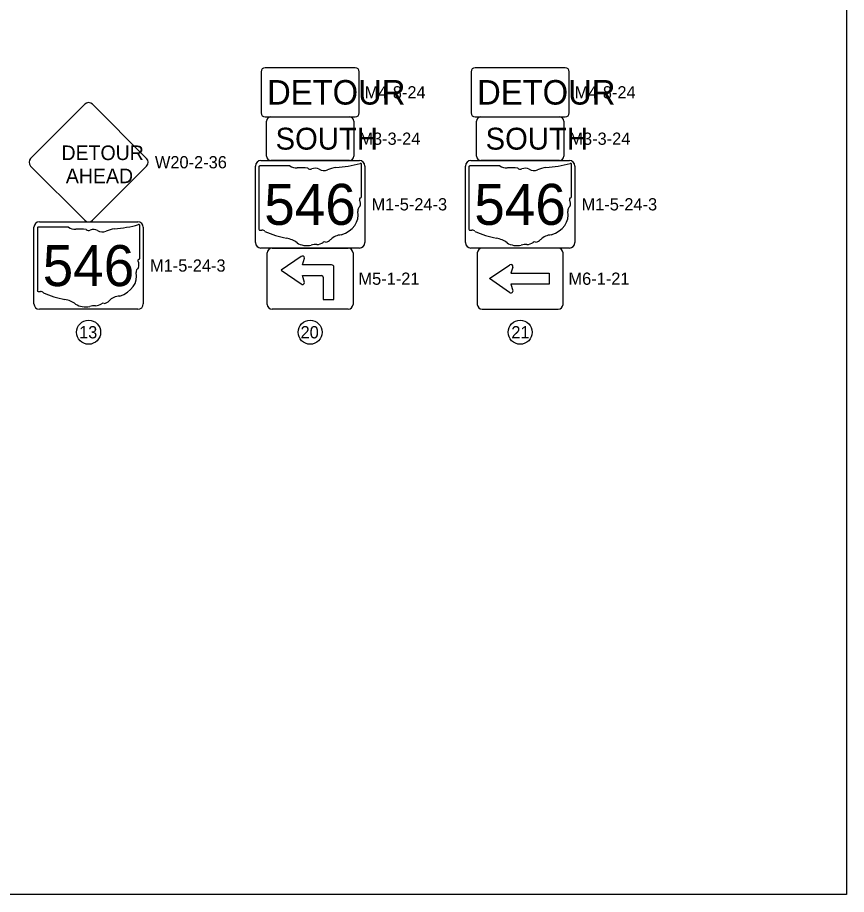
# Model space of a CAD drawing. Extents: x 40529 to 41139, y 15164 to 15584.
# Drawn here: x 40949.2 to 41138.7, y 15164.3 to 15364.8 of the extents above; entities that cross this region are included whole.
import ezdxf

# ---------------------------------------------------------------- set-up
doc = ezdxf.new("R2010")
doc.units = 0
for name, color, linetype in [('SC_Scratch1', 7, 'Continuous'), ('SH_Text', 7, 'Continuous'), ('SN_P_Signs', 7, 'Continuous'), ('SN_P_Text', 7, 'Continuous')]:
    doc.layers.add(name, color=color, linetype=linetype)

msp = doc.modelspace()

# ---------------------------------------------------------------- linework, layer by layer
at = {"layer": 'SC_Scratch1'}
msp.add_lwpolyline([(40528.65, 15584.31), (41138.65, 15584.31), (41138.65, 15164.31), (40528.65, 15164.31)], close=True, dxfattribs=at)
at = {"layer": 'SH_Text'}
for p, q in [((41007.4, 15312.09), (41024.76, 15312.09)), ((41072.76, 15312.09), (41055.4, 15312.09)), ((41072.76, 15312.09), (41072.76, 15312.09)), ((41006.28, 15299.21), (41006.28, 15310.97)), ((41014, 15310.14), (41009.43, 15307.01)), ((41025.88, 15310.97), (41025.88, 15299.21)), ((41054.28, 15310.97), (41054.28, 15299.21)), ((41073.88, 15299.21), (41073.88, 15310.97)), ((41014.33, 15308.23), (41014.8, 15309.81)), ((41020.98, 15308.23), (41014.33, 15308.23)), ((41020.98, 15308.23), (41020.98, 15308.23)), ((41057.08, 15305.09), (41061.72, 15308.27)), ((41009.43, 15307.01), (41014, 15303.88)), ((41021.51, 15300.36), (41021.51, 15307.71)), ((41062.43, 15307.75), (41061.98, 15306.31)), ((41061.98, 15306.31), (41070.73, 15306.31)), ((41070.73, 15306.31), (41070.73, 15303.86)), ((41014.8, 15304.21), (41014.33, 15305.78)), ((41014.33, 15305.78), (41018.71, 15305.78)), ((41019.06, 15305.43), (41019.06, 15300.36)), ((41061.65, 15301.95), (41057.08, 15305.09)), ((41070.73, 15303.86), (41061.98, 15303.86)), ((41061.98, 15303.86), (41062.43, 15302.42)), ((41019.06, 15300.36), (41021.51, 15300.36)), ((41019.06, 15300.36), (41021.51, 15300.36)), ((41024.76, 15298.09), (41007.4, 15298.09)), ((41055.4, 15298.09), (41072.76, 15298.09))]:
    msp.add_line(p, q, dxfattribs=at)
for points in [[(41004.88, 15352.39), (41004.88, 15342.98)], [(41026.39, 15353.29), (41005.78, 15353.29)], [(41027.28, 15342.98), (41027.28, 15352.39)], [(41052.88, 15352.39), (41052.88, 15342.98)], [(41074.39, 15353.29), (41053.78, 15353.29)], [(41075.28, 15342.98), (41075.28, 15352.39)], [(41005.78, 15342.09), (41026.39, 15342.09)], [(41053.78, 15342.09), (41074.39, 15342.09)]]:
    msp.add_lwpolyline(points, dxfattribs=at)
for centre in [(40965.45, 15292.84), (41016.08, 15292.84), (41064.08, 15292.84)]:
    msp.add_circle(centre, 2.75, dxfattribs=at)
for centre, radius, start, end in [((41005.78, 15352.39), 0.896, 90, 180), ((41026.39, 15352.39), 0.896, 0, 90), ((41053.78, 15352.39), 0.896, 90, 180), ((41074.39, 15352.39), 0.896, 0, 90), ((41005.78, 15342.98), 0.896, 180, 270), ((41026.39, 15342.98), 0.896, 270, 0), ((41053.78, 15342.98), 0.896, 180, 270), ((41074.39, 15342.98), 0.896, 270, 0), ((41007.4, 15310.97), 1.12, 90, 180), ((41024.76, 15310.97), 1.12, 0, 90), ((41055.4, 15310.97), 1.12, 90, 180), ((41072.76, 15310.97), 1.12, 0, 90), ((41014.33, 15309.81), 0.467, 0.0017, 134.9999), ((41020.98, 15307.71), 0.525, 0, 90), ((41061.98, 15307.89), 0.467, 342.7954, 124.5888), ((41014.33, 15304.21), 0.467, 225.0001, 0.0017), ((41018.71, 15305.43), 0.349, 0, 90), ((41061.98, 15302.29), 0.467, 224.9904, 17.2046), ((41007.4, 15299.21), 1.12, 180, 270), ((41024.76, 15299.21), 1.12, 270, 360), ((41055.4, 15299.21), 1.12, 180, 270), ((41072.76, 15299.21), 1.12, 270, 0)]:
    msp.add_arc(centre, radius, start, end, dxfattribs=at)
at = {"layer": 'SN_P_Signs'}
for p, q in [((41006.08, 15333.09), (41006.08, 15341.09)), ((41007.08, 15342.09), (41025.08, 15342.09)), ((41026.08, 15341.09), (41026.08, 15333.09)), ((41054.08, 15333.09), (41054.08, 15341.09)), ((41055.08, 15342.09), (41073.08, 15342.09)), ((41074.08, 15341.09), (41074.08, 15333.09)), ((41025.08, 15332.09), (41007.08, 15332.09)), ((41073.08, 15332.09), (41055.08, 15332.09)), ((41004.36, 15330.61), (41004.36, 15316.38)), ((41011.46, 15330.86), (41004.59, 15330.86)), ((41027.8, 15323.77), (41027.8, 15331.21)), ((41052.36, 15330.61), (41052.36, 15316.38)), ((41059.46, 15330.86), (41052.59, 15330.86)), ((41075.8, 15323.77), (41075.8, 15331.21)), ((41027.8, 15323.77), (41027.8, 15323.77)), ((41075.8, 15323.77), (41075.8, 15323.77)), ((40953.73, 15316.61), (40953.73, 15302.38)), ((40960.83, 15316.86), (40953.96, 15316.86)), ((40977.17, 15309.77), (40977.17, 15317.21)), ((40977.17, 15309.77), (40977.17, 15309.77))]:
    msp.add_line(p, q, dxfattribs=at)
for points in [[(40952.19, 15332.59), (40964.57, 15344.97)], [(40966.34, 15344.97), (40978.71, 15332.59)], [(41004.83, 15332.09), (41027.33, 15332.09)], [(41052.83, 15332.09), (41075.33, 15332.09)], [(40964.57, 15318.45), (40952.19, 15330.83)], [(40978.71, 15330.83), (40966.34, 15318.45)], [(41003.58, 15313.34), (41003.58, 15330.84)], [(41028.58, 15330.84), (41028.58, 15313.34)], [(41051.58, 15313.34), (41051.58, 15330.84)], [(41076.58, 15330.84), (41076.58, 15313.34)], [(40954.2, 15318.09), (40976.7, 15318.09)], [(40952.95, 15299.34), (40952.95, 15316.84)], [(40977.95, 15316.84), (40977.95, 15299.34)], [(41027.33, 15312.09), (41004.83, 15312.09)], [(41075.33, 15312.09), (41052.83, 15312.09)], [(40976.7, 15298.09), (40954.2, 15298.09)]]:
    msp.add_lwpolyline(points, dxfattribs=at)
for centre, radius, start, end in [((40965.45, 15344.08), 1.25, 45, 135), ((41007.08, 15341.08), 1, 90, 180), ((41025.08, 15341.08), 1, 0, 90), ((41055.08, 15341.08), 1, 90, 180), ((41073.08, 15341.08), 1, 0, 90), ((40953.08, 15331.71), 1.25, 135, 225), ((40977.83, 15331.71), 1.25, 315, 45), ((41004.83, 15330.84), 1.25, 90, 180), ((41007.08, 15333.08), 1, 180, 270), ((41025.08, 15333.08), 1, 270, 0), ((41027.33, 15330.84), 1.25, 0, 90), ((41052.83, 15330.84), 1.25, 90, 180), ((41055.08, 15333.08), 1, 180, 270), ((41073.08, 15333.08), 1, 270, 0), ((41075.33, 15330.84), 1.25, 0, 90), ((40954.2, 15316.84), 1.25, 90, 180), ((40965.45, 15319.34), 1.25, 225, 315), ((40976.7, 15316.84), 1.25, 0, 90), ((41004.83, 15313.34), 1.25, 180, 270), ((41027.33, 15313.34), 1.25, 270, 0), ((41052.83, 15313.34), 1.25, 180, 270), ((41075.33, 15313.34), 1.25, 270, 0), ((40954.2, 15299.34), 1.25, 180, 270), ((40976.7, 15299.34), 1.25, 270, 0)]:
    msp.add_arc(centre, radius, start, end, dxfattribs=at)
for centre, major_axis, start_param, end_param in [((41004.63, 15330.64), (0.272, 0), 1.712693, 3.28349), ((41013.09, 15332.51), (2.63, 0), 4.042523, 4.731795), ((41013.97, 15322.87), (9.45, 0), 1.404758, 1.657858), ((41016.11, 15330.72), (0.76, 0), 3.836095, 5.185415), ((41017.23, 15329.07), (1.58, 0), 0.950623, 2.079405), ((41019.27, 15331.33), (1.9, 0), 4.081561, 5.145723), ((41022.62, 15326.51), (5, 0), 1.699011, 2.107814), ((41019.45, 15350.26), (24.85, 0), 4.814394, 5.042369), ((41027.54, 15331.24), (0.261, 0), 6.141152, 7.989035), ((41052.63, 15330.64), (0.272, 0), 1.712693, 3.28349), ((41061.09, 15332.51), (2.63, 0), 4.042523, 4.731795), ((41061.97, 15322.87), (9.45, 0), 1.404758, 1.657858), ((41064.11, 15330.72), (0.76, 0), 3.836095, 5.185415), ((41065.23, 15329.07), (1.58, 0), 0.950623, 2.079405), ((41067.27, 15331.33), (1.9, 0), 4.081561, 5.145723), ((41070.62, 15326.51), (5, 0), 1.699011, 2.107814), ((41067.45, 15350.26), (24.85, 0), 4.814394, 5.042369), ((41075.54, 15331.24), (0.261, 0), 6.141152, 7.989035), ((41027.74, 15323.22), (0.404, 0), 1.883978, 3.671073), ((41025.17, 15322.28), (2.42, 0), 5.934695, 6.695948), ((41027.52, 15323.74), (0.279, 0), 5.05454, 6.418171), ((41075.74, 15323.22), (0.404, 0), 1.883978, 3.671073), ((41073.17, 15322.28), (2.42, 0), 5.934695, 6.695948), ((41075.52, 15323.74), (0.279, 0), 5.05454, 6.418171), ((41020.84, 15319.7), (6.22, 0), 5.101752, 6.440018), ((41028.74, 15320.65), (1.76, 0), 2.387724, 3.262537), ((41068.84, 15319.7), (6.22, 0), 5.101752, 6.440018), ((41076.74, 15320.65), (1.76, 0), 2.387724, 3.262537), ((40954, 15316.64), (0.272, 0), 1.712693, 3.28349), ((40962.46, 15318.51), (2.63, 0), 4.042523, 4.731795), ((40963.33, 15308.87), (9.45, 0), 1.404758, 1.657858), ((40965.48, 15316.72), (0.76, 0), 3.836095, 5.185415), ((40966.6, 15315.07), (1.58, 0), 0.950623, 2.079405), ((40968.63, 15317.33), (1.9, 0), 4.081561, 5.145723), ((40971.99, 15312.51), (5, 0), 1.699011, 2.107814), ((40968.82, 15336.26), (24.85, 0), 4.814394, 5.042369), ((40976.91, 15317.24), (0.261, 0), 6.141152, 7.989035), ((41004.63, 15316.35), (0.274, 0), 3.00124, 4.508301), ((41004.68, 15317.81), (2.09, 0), 4.665946, 4.897461), ((41005.1, 15315.56), (0.754, 0), 0.519207, 1.627899), ((41052.63, 15316.35), (0.274, 0), 3.00124, 4.508301), ((41052.68, 15317.81), (2.09, 0), 4.665946, 4.897461), ((41053.1, 15315.56), (0.754, 0), 0.519207, 1.627899), ((41014.62, 15328.35), (17.95, 0), 4.195997, 4.488961), ((41009.27, 15309.99), (5.62, 0), 0.823519, 1.323587), ((41019.15, 15315), (2.01, 0), 4.937069, 5.64225), ((41023.47, 15312.39), (3.4, 0), 1.647645, 2.488434), ((41062.62, 15328.35), (17.95, 0), 4.195997, 4.488961), ((41057.27, 15309.99), (5.62, 0), 0.823519, 1.323587), ((41067.15, 15315), (2.01, 0), 4.937069, 5.64225), ((41071.47, 15312.39), (3.4, 0), 1.647645, 2.488434), ((41015.34, 15315.49), (3.56, 0), 4.026481, 4.996735), ((41017.4, 15310.57), (2.93, 0), 1.495662, 1.94098), ((41017.66, 15314.43), (1.9, 0), 4.691044, 5.507374), ((41019.38, 15313.05), (0.535, 0), 1.147584, 2.315152), ((41063.34, 15315.49), (3.56, 0), 4.026481, 4.996735), ((41065.4, 15310.57), (2.93, 0), 1.495662, 1.94098), ((41065.66, 15314.43), (1.9, 0), 4.691044, 5.507374), ((41067.38, 15313.05), (0.535, 0), 1.147584, 2.315152), ((40977.11, 15309.22), (0.404, 0), 1.883978, 3.671073), ((40974.54, 15308.28), (2.42, 0), 5.934695, 6.695948), ((40976.89, 15309.74), (0.279, 0), 5.05454, 6.418171), ((40970.21, 15305.7), (6.22, 0), 5.101752, 6.440018), ((40978.1, 15306.65), (1.76, 0), 2.387724, 3.262537), ((40954, 15302.35), (0.274, 0), 3.00124, 4.508301), ((40954.04, 15303.81), (2.09, 0), 4.665946, 4.897461), ((40954.47, 15301.56), (0.754, 0), 0.519207, 1.627899), ((40963.99, 15314.35), (17.95, 0), 4.195997, 4.488961), ((40958.64, 15295.99), (5.62, 0), 0.823519, 1.323587), ((40968.52, 15301), (2.01, 0), 4.937069, 5.64225), ((40972.83, 15298.39), (3.4, 0), 1.647645, 2.488434), ((40964.71, 15301.49), (3.56, 0), 4.026481, 4.996735), ((40966.77, 15296.57), (2.93, 0), 1.495662, 1.94098), ((40967.03, 15300.43), (1.9, 0), 4.691044, 5.507374), ((40968.75, 15299.05), (0.535, 0), 1.147584, 2.315152)]:
    msp.add_ellipse(centre, major_axis=major_axis, ratio=0.8, start_param=start_param, end_param=end_param, dxfattribs=at)

# ---------------------------------------------------------------- texts
at = {"layer": 'SH_Text'}
for s, height, p in [('DETOUR', 5.6, (41006.24, 15344.89)), ('DETOUR', 5.6, (41054.24, 15344.89)), ('M4-8-24', 2.8, (41028.52, 15346.29)), ('M4-8-24', 2.8, (41076.52, 15346.29)), ('W20-2-36', 2.8, (40980.6, 15330.31)), ('M5-1-21', 2.8, (41027.12, 15303.69)), ('M6-1-21', 2.8, (41075.12, 15303.69)), ('13', 2.8, (40963.27, 15291.44)), ('20', 2.8, (41013.89, 15291.44)), ('21', 2.8, (41062.06, 15291.44))]:
    msp.add_text(s, height=height, dxfattribs=at).set_placement(p)
at = {"layer": 'SN_P_Signs'}
for s, height, p in [('SOUTH', 5, (41008.17, 15334.59)), ('SOUTH', 5, (41056.17, 15334.59)), ('DETOUR', 3.333, (40959.25, 15332.2)), ('AHEAD', 3.333, (40960.25, 15326.92)), ('546', 9.375, (41005.59, 15317.39)), ('546', 9.375, (41053.59, 15317.39)), ('546', 9.375, (40954.96, 15303.39))]:
    msp.add_text(s, height=height, dxfattribs=at).set_placement(p)
at = {"layer": 'SN_P_Text'}
for s, p in [('M3-3-24', (41027.32, 15335.69)), ('M3-3-24', (41075.32, 15335.69)), ('M1-5-24-3', (41030.11, 15320.69)), ('M1-5-24-3', (41078.11, 15320.69)), ('M1-5-24-3', (40979.48, 15306.69))]:
    msp.add_text(s, height=2.8, dxfattribs=at).set_placement(p)

doc.saveas('drawing.dxf')
